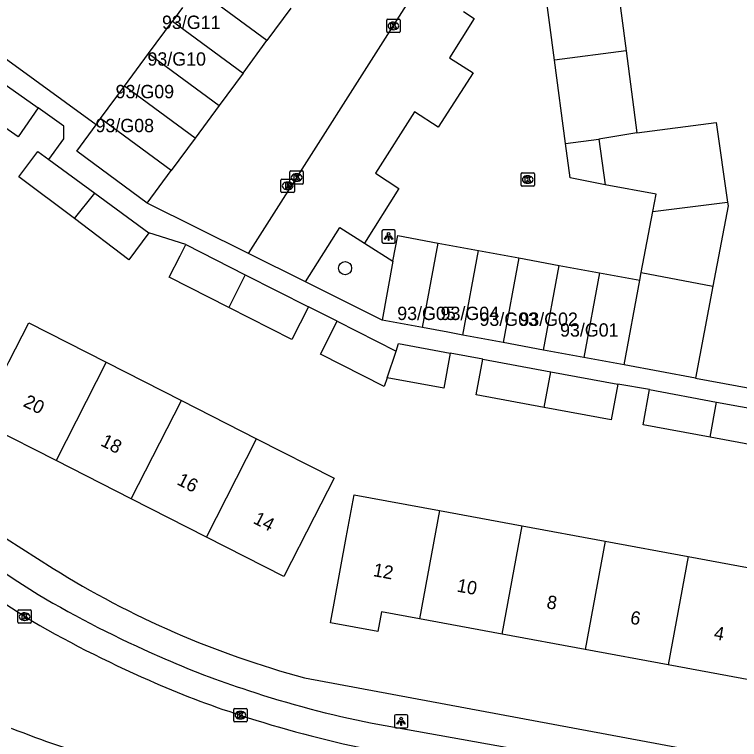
# Model space of a CAD drawing. Extents: x 160557 to 161245, y 385330 to 386505.
# Drawn here: x 161001.8 to 161056.2, y 385939.3 to 385993.6 of the extents above; entities that cross this region are included whole.
import ezdxf

# ---------------------------------------------------------------- set-up
doc = ezdxf.new("R2010")
doc.units = 0
for name, color, linetype in [('IMGEO_Boom', 7, 'Continuous'), ('IMGEO_Kolk', 7, 'Continuous'), ('IMGEO_Lichtpunt', 7, 'Continuous'), ('IMGEO_Pand', 7, 'Continuous'), ('IMGEO_Pand_nummerreeks', 7, 'Continuous'), ('IMGEO_Rijbaan_lokaal_open', 7, 'Continuous'), ('IMGEO_Rioolput', 7, 'Continuous'), ('IMGEO_Voetpad_gesloten', 7, 'Continuous'), ('IMGEO_Voetpad_open', 7, 'Continuous')]:
    doc.layers.add(name, color=color, linetype=linetype)

msp = doc.modelspace()

# ---------------------------------------------------------------- linework, layer by layer
at = {"layer": 'IMGEO_Boom'}
msp.add_circle((161026.612, 385974.634), 0.489, dxfattribs=at)
at = {"layer": 'IMGEO_Kolk'}
for p, q in [((161029.73, 385992.364), (161029.73, 385993.216)), ((161029.805, 385993.29), (161030.657, 385993.29)), ((161030.731, 385993.216), (161030.731, 385992.364)), ((161030.218, 385993.07), (161030.243, 385993.07)), ((161030.657, 385992.29), (161029.805, 385992.29)), ((161030.241, 385992.51), (161030.216, 385992.51)), ((161022.477, 385981.004), (161022.477, 385981.856)), ((161022.552, 385981.93), (161023.404, 385981.93)), ((161022.965, 385981.71), (161022.99, 385981.71)), ((161023.478, 385981.856), (161023.478, 385981.004)), ((161039.806, 385980.848), (161039.806, 385981.7)), ((161039.881, 385981.774), (161040.733, 385981.774)), ((161040.807, 385981.7), (161040.807, 385980.848)), ((161022.988, 385981.15), (161022.963, 385981.15)), ((161040.294, 385981.554), (161040.319, 385981.554)), ((161023.404, 385980.93), (161022.552, 385980.93)), ((161040.733, 385980.774), (161039.881, 385980.774)), ((161040.317, 385980.994), (161040.292, 385980.994)), ((161002.077, 385948.088), (161002.077, 385948.94)), ((161002.152, 385949.014), (161003.004, 385949.014)), ((161002.565, 385948.794), (161002.59, 385948.794)), ((161003.078, 385948.94), (161003.078, 385948.088)), ((161003.004, 385948.014), (161002.152, 385948.014)), ((161002.588, 385948.234), (161002.563, 385948.234)), ((161018.255, 385940.702), (161018.255, 385941.554)), ((161018.33, 385941.628), (161019.182, 385941.628)), ((161019.256, 385941.554), (161019.256, 385940.702)), ((161018.743, 385941.408), (161018.768, 385941.408)), ((161019.182, 385940.628), (161018.33, 385940.628)), ((161018.766, 385940.848), (161018.741, 385940.848))]:
    msp.add_line(p, q, dxfattribs=at)
for points in [[(161029.73, 385992.364), (161029.73, 385993.216)], [(161029.805, 385993.29), (161030.657, 385993.29)], [(161030.731, 385993.216), (161030.731, 385992.364)], [(161030.051, 385992.99), (161030.174, 385992.99), (161030.174, 385992.839), (161030.304, 385992.99), (161030.468, 385992.99), (161030.322, 385992.839), (161030.475, 385992.59), (161030.323, 385992.59), (161030.238, 385992.754), (161030.174, 385992.687), (161030.174, 385992.59), (161030.051, 385992.59), (161030.051, 385992.99)], [(161030.657, 385992.29), (161029.805, 385992.29)], [(161022.477, 385981.004), (161022.477, 385981.856)], [(161022.552, 385981.93), (161023.404, 385981.93)], [(161023.478, 385981.856), (161023.478, 385981.004)], [(161039.806, 385980.848), (161039.806, 385981.7)], [(161039.881, 385981.774), (161040.733, 385981.774)], [(161040.807, 385981.7), (161040.807, 385980.848)], [(161022.798, 385981.63), (161022.921, 385981.63), (161022.921, 385981.479), (161023.051, 385981.63), (161023.215, 385981.63), (161023.069, 385981.479), (161023.222, 385981.23), (161023.07, 385981.23), (161022.985, 385981.394), (161022.921, 385981.327), (161022.921, 385981.23), (161022.798, 385981.23), (161022.798, 385981.63)], [(161040.127, 385981.474), (161040.25, 385981.474), (161040.25, 385981.323), (161040.38, 385981.474), (161040.544, 385981.474), (161040.398, 385981.323), (161040.551, 385981.074), (161040.399, 385981.074), (161040.314, 385981.238), (161040.25, 385981.171), (161040.25, 385981.074), (161040.127, 385981.074), (161040.127, 385981.474)], [(161023.404, 385980.93), (161022.552, 385980.93)], [(161040.733, 385980.774), (161039.881, 385980.774)], [(161002.077, 385948.088), (161002.077, 385948.94)], [(161002.152, 385949.014), (161003.004, 385949.014)], [(161002.398, 385948.714), (161002.521, 385948.714), (161002.521, 385948.563), (161002.651, 385948.714), (161002.815, 385948.714), (161002.669, 385948.563), (161002.822, 385948.314), (161002.67, 385948.314), (161002.585, 385948.478), (161002.521, 385948.411), (161002.521, 385948.314), (161002.398, 385948.314), (161002.398, 385948.714)], [(161003.078, 385948.94), (161003.078, 385948.088)], [(161003.004, 385948.014), (161002.152, 385948.014)], [(161018.255, 385940.702), (161018.255, 385941.554)], [(161018.33, 385941.628), (161019.182, 385941.628)], [(161019.256, 385941.554), (161019.256, 385940.702)], [(161018.576, 385941.328), (161018.699, 385941.328), (161018.699, 385941.177), (161018.829, 385941.328), (161018.993, 385941.328), (161018.847, 385941.177), (161019, 385940.928), (161018.848, 385940.928), (161018.763, 385941.092), (161018.699, 385941.025), (161018.699, 385940.928), (161018.576, 385940.928), (161018.576, 385941.328)], [(161019.182, 385940.628), (161018.33, 385940.628)]]:
    msp.add_lwpolyline(points, dxfattribs=at)
for centre, start, end in [((161029.807, 385993.214), 91.552, 178.448), ((161029.807, 385993.214), 91.552, 178.448), ((161030.655, 385993.214), 1.552, 88.448), ((161030.655, 385993.214), 1.552, 88.448), ((161029.807, 385992.366), 181.552, 268.448), ((161029.807, 385992.366), 181.552, 268.448), ((161030.655, 385992.366), 271.552, 358.448), ((161030.655, 385992.366), 271.552, 358.448), ((161022.554, 385981.854), 91.552, 178.448), ((161022.554, 385981.854), 91.552, 178.448), ((161023.402, 385981.854), 1.552, 88.448), ((161023.402, 385981.854), 1.552, 88.448), ((161039.883, 385981.698), 91.552, 178.448), ((161039.883, 385981.698), 91.552, 178.448), ((161040.731, 385981.698), 1.552, 88.448), ((161040.731, 385981.698), 1.552, 88.448), ((161022.554, 385981.006), 181.552, 268.448), ((161022.554, 385981.006), 181.552, 268.448), ((161023.402, 385981.006), 271.552, 358.448), ((161023.402, 385981.006), 271.552, 358.448), ((161039.883, 385980.85), 181.552, 268.448), ((161039.883, 385980.85), 181.552, 268.448), ((161040.731, 385980.85), 271.552, 358.448), ((161040.731, 385980.85), 271.552, 358.448), ((161002.154, 385948.938), 91.552, 178.448), ((161002.154, 385948.938), 91.552, 178.448), ((161003.002, 385948.938), 1.552, 88.448), ((161003.002, 385948.938), 1.552, 88.448), ((161002.154, 385948.09), 181.552, 268.448), ((161002.154, 385948.09), 181.552, 268.448), ((161003.002, 385948.09), 271.552, 358.448), ((161003.002, 385948.09), 271.552, 358.448), ((161018.332, 385941.552), 91.552, 178.448), ((161018.332, 385941.552), 91.552, 178.448), ((161019.18, 385941.552), 1.552, 88.448), ((161019.18, 385941.552), 1.552, 88.448), ((161018.332, 385940.704), 181.552, 268.448), ((161018.332, 385940.704), 181.552, 268.448), ((161019.18, 385940.704), 271.552, 358.448), ((161019.18, 385940.704), 271.552, 358.448)]:
    msp.add_arc(centre, 0.0765, start, end, dxfattribs=at)
for centre, major_axis, ratio, start_param, end_param in [((161030.217, 385992.79), (-0.387, 0.002), 0.722429, 4.712389, 7.853982), ((161030.242, 385992.79), (-0.39, 0.002), 0.717154, 1.570796, 4.712389), ((161022.964, 385981.43), (-0.387, 0.002), 0.722429, 4.712389, 7.853982), ((161022.989, 385981.43), (-0.39, 0.002), 0.717154, 1.570796, 4.712389), ((161040.293, 385981.274), (-0.387, 0.002), 0.722429, 4.712389, 7.853982), ((161040.318, 385981.274), (-0.39, 0.002), 0.717154, 1.570796, 4.712389), ((161002.564, 385948.514), (-0.387, 0.002), 0.722429, 4.712389, 7.853982), ((161002.589, 385948.514), (-0.39, 0.002), 0.717154, 1.570796, 4.712389), ((161018.742, 385941.128), (-0.387, 0.002), 0.722429, 4.712389, 7.853982), ((161018.767, 385941.128), (-0.39, 0.002), 0.717154, 1.570796, 4.712389)]:
    msp.add_ellipse(centre, major_axis=major_axis, ratio=ratio, start_param=start_param, end_param=end_param, dxfattribs=at)
at = {"layer": 'IMGEO_Lichtpunt'}
for p, q in [((161029.378, 385977.415), (161029.378, 385976.608)), ((161029.378, 385977.415), (161029.378, 385976.608)), ((161030.28, 385977.51), (161029.472, 385977.51)), ((161030.28, 385977.51), (161029.472, 385977.51)), ((161030.374, 385976.608), (161030.374, 385977.415)), ((161030.374, 385976.608), (161030.374, 385977.415)), ((161029.472, 385976.514), (161030.28, 385976.514)), ((161029.472, 385976.514), (161030.28, 385976.514)), ((161030.313, 385941.068), (161030.313, 385940.261)), ((161030.313, 385941.068), (161030.313, 385940.261)), ((161031.215, 385941.163), (161030.407, 385941.163)), ((161031.215, 385941.163), (161030.407, 385941.163)), ((161031.309, 385940.261), (161031.309, 385941.068)), ((161031.309, 385940.261), (161031.309, 385941.068)), ((161030.407, 385940.167), (161031.215, 385940.167)), ((161030.407, 385940.167), (161031.215, 385940.167))]:
    msp.add_line(p, q, dxfattribs=at)
for points in [[(161029.752, 385977.079), (161029.791, 385977.051), (161029.603, 385976.789), (161029.565, 385976.816), (161029.752, 385977.079)], [(161029.854, 385977.031), (161029.901, 385977.031), (161029.901, 385976.709), (161029.854, 385976.709), (161029.854, 385977.031)], [(161029.964, 385977.051), (161030.002, 385977.078), (161030.189, 385976.816), (161030.15, 385976.788), (161029.964, 385977.051)], [(161030.687, 385940.732), (161030.726, 385940.704), (161030.538, 385940.442), (161030.5, 385940.469), (161030.687, 385940.732)], [(161030.789, 385940.684), (161030.836, 385940.684), (161030.836, 385940.362), (161030.789, 385940.362), (161030.789, 385940.684)], [(161030.899, 385940.704), (161030.937, 385940.731), (161031.124, 385940.469), (161031.085, 385940.441), (161030.899, 385940.704)]]:
    msp.add_lwpolyline(points, dxfattribs=at)
for centre in [(161029.877, 385977.213), (161030.812, 385940.866)]:
    msp.add_circle(centre, 0.0994, dxfattribs=at)
for centre, start, end in [((161029.472, 385977.415), 90, 180), ((161029.472, 385977.415), 90, 180), ((161030.28, 385977.415), 0, 90), ((161030.28, 385977.415), 0, 90), ((161029.472, 385976.608), 180, 270), ((161029.472, 385976.608), 180, 270), ((161030.28, 385976.608), 270, 0), ((161030.28, 385976.608), 270, 360), ((161030.407, 385941.068), 90, 180), ((161030.407, 385941.068), 90, 180), ((161031.215, 385941.068), 0, 90), ((161031.215, 385941.068), 0, 90), ((161030.407, 385940.261), 180, 270), ((161030.407, 385940.261), 180, 270), ((161031.215, 385940.261), 270, 0), ((161031.215, 385940.261), 270, 360)]:
    msp.add_arc(centre, 0.0946, start, end, dxfattribs=at)
at = {"layer": 'IMGEO_Pand'}
for points in [[(161046.901, 385996.967), (161047.692, 385990.916)], [(161042.325, 385990.226), (161041.525, 385996.276)], [(161020.75, 385991.692), (161015.459, 385995.591)], [(161014.411, 385994.169), (161013.663, 385993.154)], [(161022.545, 385994.13), (161020.75, 385991.692)], [(161011.867, 385990.717), (161013.663, 385993.154)], [(161013.663, 385993.154), (161018.954, 385989.255)], [(161018.954, 385989.255), (161020.75, 385991.692)], [(161047.692, 385990.916), (161042.325, 385990.226)], [(161047.692, 385990.916), (161048.495, 385984.776)], [(161010.071, 385988.279), (161011.867, 385990.717)], [(161011.867, 385990.717), (161017.158, 385986.818)], [(161043.151, 385983.98), (161042.325, 385990.226)], [(161003.588, 385986.655), (161002.082, 385984.482), (161000, 385985.928), (160997.653, 385987.558), (160999.244, 385989.717)], [(160999.244, 385989.717), (161000, 385989.184), (161003.588, 385986.655)], [(161018.954, 385989.255), (161017.158, 385986.818)], [(161008.275, 385985.842), (161010.071, 385988.279)], [(161015.362, 385984.381), (161010.071, 385988.279)], [(161017.158, 385986.818), (161015.362, 385984.381)], [(161007.936, 385985.383), (161008.153, 385985.677), (161008.275, 385985.842)], [(161013.566, 385981.943), (161008.275, 385985.842)], [(161048.495, 385984.776), (161054.445, 385985.554), (161055.293, 385979.589)], [(161011.77, 385979.506), (161007.745, 385982.472), (161006.479, 385983.405), (161007.936, 385985.383)], [(161015.362, 385984.381), (161013.566, 385981.943)], [(161048.495, 385984.776), (161045.648, 385984.299)], [(161043.151, 385983.98), (161045.648, 385984.299)], [(161045.648, 385984.299), (161046.119, 385980.889)], [(161006.305, 385978.366), (161002.142, 385981.474), (161003.578, 385983.383), (161004.39, 385982.787)], [(161004.39, 385982.787), (161007.836, 385980.257)], [(161011.77, 385979.506), (161013.566, 385981.943)], [(161049.696, 385978.869), (161049.946, 385980.185), (161046.119, 385980.889)], [(161006.305, 385978.366), (161007.836, 385980.257)], [(161007.836, 385980.257), (161011.882, 385977.286)], [(161049.696, 385978.869), (161055.293, 385979.589)], [(161055.293, 385979.589), (161055.333, 385979.308), (161054.187, 385973.279)], [(161048.827, 385974.296), (161049.696, 385978.869)], [(161011.882, 385977.286), (161010.398, 385975.266), (161006.305, 385978.366)], [(161030.202, 385975.145), (161030.559, 385977.077), (161033.586, 385976.518)], [(161017.879, 385971.686), (161013.42, 385973.955), (161014.229, 385975.546), (161014.667, 385976.406)], [(161014.667, 385976.406), (161019.126, 385974.138)], [(161032.414, 385970.174), (161033.586, 385976.518)], [(161033.586, 385976.518), (161036.612, 385975.96)], [(161035.441, 385969.615), (161036.612, 385975.96)], [(161036.612, 385975.96), (161039.638, 385975.401)], [(161030.202, 385975.145), (161029.388, 385970.733)], [(161039.638, 385975.401), (161038.467, 385969.057)], [(161039.638, 385975.401), (161042.665, 385974.842)], [(161041.494, 385968.498), (161042.665, 385974.842)], [(161042.665, 385974.842), (161045.692, 385974.284)], [(161019.126, 385974.138), (161017.879, 385971.686)], [(161019.126, 385974.138), (161023.861, 385971.729)], [(161045.692, 385974.284), (161044.52, 385967.94)], [(161045.692, 385974.284), (161048.718, 385973.725)], [(161048.718, 385973.725), (161048.827, 385974.296)], [(161048.827, 385974.296), (161054.187, 385973.279)], [(161047.548, 385967.381), (161048.718, 385973.725)], [(161054.187, 385973.279), (161052.879, 385966.397)], [(161023.861, 385971.729), (161022.614, 385969.277), (161017.879, 385971.686)], [(161004.933, 385960.205), (161000, 385962.715), (160999.132, 385963.156), (161000, 385964.863), (161001.399, 385967.613), (161002.886, 385970.536), (161008.686, 385967.585)], [(161029.767, 385966.417), (161029.547, 385965.758), (161024.756, 385968.196), (161026.011, 385970.663)], [(161026.011, 385970.663), (161030.433, 385968.413)], [(161032.414, 385970.174), (161029.388, 385970.733)], [(161035.441, 385969.615), (161034.305, 385969.825), (161032.414, 385970.174)], [(161038.467, 385969.057), (161035.441, 385969.615)], [(161030.433, 385968.413), (161030.622, 385968.978), (161034.5, 385968.262)], [(161041.494, 385968.498), (161038.467, 385969.057)], [(161029.767, 385966.417), (161030.433, 385968.413)], [(161034.5, 385968.262), (161034.014, 385965.633), (161029.767, 385966.417)], [(161044.52, 385967.94), (161041.494, 385968.498)], [(161008.686, 385967.585), (161004.933, 385960.205)], [(161008.686, 385967.585), (161014.332, 385964.713)], [(161041.537, 385964.2), (161036.448, 385965.14), (161036.943, 385967.815)], [(161036.943, 385967.815), (161042.031, 385966.874)], [(161047.548, 385967.381), (161044.52, 385967.94)], [(161052.879, 385966.397), (161047.548, 385967.381)], [(161041.537, 385964.2), (161042.031, 385966.874)], [(161042.031, 385966.874), (161047.069, 385965.943)], [(161047.069, 385965.943), (161046.574, 385963.269), (161041.537, 385964.2)], [(161053.984, 385961.964), (161048.954, 385962.894), (161049.441, 385965.527)], [(161049.441, 385965.527), (161054.471, 385964.597)], [(161010.578, 385957.333), (161014.332, 385964.713)], [(161014.332, 385964.713), (161019.977, 385961.842)], [(161053.984, 385961.964), (161054.471, 385964.597)], [(161054.471, 385964.597), (161059.585, 385963.652)], [(161059.585, 385963.652), (161059.099, 385961.019), (161053.984, 385961.964)], [(161019.977, 385961.842), (161025.781, 385958.889), (161024.294, 385955.966), (161022.026, 385951.509), (161016.224, 385954.461)], [(161016.224, 385954.461), (161019.977, 385961.842)], [(161010.578, 385957.333), (161004.933, 385960.205)], [(161016.224, 385954.461), (161010.578, 385957.333)], [(161032.179, 385948.345), (161029.332, 385948.871), (161029.059, 385947.396), (161025.519, 385948.05), (161025.792, 385949.525), (161026.701, 385954.442), (161027.294, 385957.653), (161033.68, 385956.473)], [(161033.68, 385956.473), (161032.179, 385948.345)], [(161033.68, 385956.473), (161039.898, 385955.324)], [(161038.397, 385947.196), (161039.898, 385955.324)], [(161039.898, 385955.324), (161046.116, 385954.175)], [(161046.116, 385954.175), (161044.615, 385946.047)], [(161046.116, 385954.175), (161052.333, 385953.026)], [(161052.333, 385953.026), (161050.832, 385944.898)], [(161052.333, 385953.026), (161058.551, 385951.877)], [(161038.397, 385947.196), (161032.179, 385948.345)], [(161044.615, 385946.047), (161038.397, 385947.196)], [(161050.832, 385944.898), (161044.615, 385946.047)], [(161057.05, 385943.749), (161050.832, 385944.898)]]:
    msp.add_lwpolyline(points, dxfattribs=at)
at = {"layer": 'IMGEO_Rijbaan_lokaal_open'}
for points in [[(161019.362, 385975.725), (161032.442, 385996.293)], [(161035.482, 385993.862), (161036.297, 385993.354), (161034.444, 385990.41), (161036.209, 385989.28), (161033.603, 385985.194), (161031.813, 385986.345), (161028.881, 385981.746), (161030.635, 385980.609), (161028.054, 385976.511)], [(161046.119, 385980.889), (161043.5, 385981.394), (161043.151, 385983.98)], [(161019.362, 385975.725), (161011.77, 385979.506)], [(161028.054, 385976.511), (161030.202, 385975.145)], [(161002.589, 385948.505), (160999.999, 385950.177), (160998.189, 385951.341), (160986.724, 385958.988), (160973.667, 385967.66)]]:
    msp.add_lwpolyline(points, dxfattribs=at)
for centre, radius, start, end in [((161046.652, 386023.307), 86.816, 239.49922, 246.411), ((161039.17, 386004.728), 66.797, 245.91547, 252.20158), ((161044.383, 386018.65), 81.65, 251.7048, 258.62704), ((161031.746, 386016.467), 82.062, 248.41375, 259.00106)]:
    msp.add_arc(centre, radius, start, end, dxfattribs=at)
at = {"layer": 'IMGEO_Rioolput'}
for p, q in [((161021.803, 385980.375), (161021.803, 385981.227)), ((161021.878, 385981.301), (161022.73, 385981.301)), ((161022.804, 385981.227), (161022.804, 385980.375)), ((161022.291, 385981.081), (161022.316, 385981.081)), ((161022.73, 385980.301), (161021.878, 385980.301)), ((161022.314, 385980.521), (161022.289, 385980.521))]:
    msp.add_line(p, q, dxfattribs=at)
for points in [[(161021.803, 385980.375), (161021.803, 385981.227)], [(161021.878, 385981.301), (161022.73, 385981.301)], [(161022.804, 385981.227), (161022.804, 385980.375)], [(161022.392, 385980.999), (161022.14, 385981.001), (161022.14, 385980.601)], [(161022.14, 385980.601), (161022.264, 385980.601), (161022.264, 385980.763), (161022.275, 385980.763)], [(161022.318, 385980.92), (161022.264, 385980.92), (161022.264, 385980.839)], [(161022.264, 385980.839), (161022.316, 385980.839)], [(161022.322, 385980.734), (161022.393, 385980.601), (161022.533, 385980.601), (161022.468, 385980.727)], [(161022.73, 385980.301), (161021.878, 385980.301)]]:
    msp.add_lwpolyline(points, dxfattribs=at)
for centre, radius, start, end in [((161021.88, 385981.225), 0.0765, 91.552, 178.448), ((161021.88, 385981.225), 0.0765, 91.552, 178.448), ((161022.728, 385981.225), 0.0765, 1.552, 88.448), ((161022.728, 385981.225), 0.0765, 1.552, 88.448), ((161022.274, 385980.71), 0.0533, 26.0293, 88.6989), ((161022.3, 385981.028), 0.19, 274.7715, 282.9687), ((161022.324, 385980.824), 0.0964, 77.0061, 93.1865), ((161022.338, 385980.881), 0.0378, 276.6634, 79.6772), ((161022.391, 385980.889), 0.109, 350.3612, 89.416), ((161022.389, 385980.889), 0.112, 277.5842, 350.9817), ((161022.373, 385980.674), 0.108, 29.5134, 73.7905), ((161021.88, 385980.377), 0.0765, 181.552, 268.448), ((161021.88, 385980.377), 0.0765, 181.552, 268.448), ((161022.728, 385980.377), 0.0765, 271.552, 358.448), ((161022.728, 385980.377), 0.0765, 271.552, 358.448)]:
    msp.add_arc(centre, radius, start, end, dxfattribs=at)
for centre, major_axis, ratio, start_param, end_param in [((161022.29, 385980.801), (-0.387, 0.002), 0.722429, 4.712389, 7.853982), ((161022.315, 385980.801), (-0.39, 0.002), 0.717154, 1.570796, 4.712389)]:
    msp.add_ellipse(centre, major_axis=major_axis, ratio=ratio, start_param=start_param, end_param=end_param, dxfattribs=at)
at = {"layer": 'IMGEO_Voetpad_gesloten'}
for points in [[(161007.936, 385985.383), (160994.121, 385995.449)], [(161004.39, 385982.787), (161005.527, 385984.336), (161005.527, 385985.288), (161003.588, 385986.655)], [(161014.667, 385976.406), (161011.882, 385977.286)], [(161023.629, 385973.601), (161019.362, 385975.725)], [(161029.388, 385970.733), (161023.629, 385973.601)], [(161026.011, 385970.663), (161023.861, 385971.729)], [(161036.943, 385967.815), (161034.5, 385968.262)], [(161049.441, 385965.527), (161047.069, 385965.943)], [(161052.879, 385966.397), (161063.228, 385964.5)]]:
    msp.add_lwpolyline(points, dxfattribs=at)
at = {"layer": 'IMGEO_Voetpad_open'}
for points in [[(161023.629, 385973.601), (161026.208, 385977.691), (161028.054, 385976.511)], [(160972.379, 385973.71), (161000, 385955.113), (161004.713, 385952.127)], [(160977.636, 385967.398), (160987.82, 385960.634), (161000, 385952.51), (161001.799, 385951.331), (161003.597, 385950.169)], [(161023.564, 385943.934), (161062.346, 385936.7), (161063.954, 385936.4), (161074.492, 385934.434)], [(161028.631, 385940.519), (161053.33, 385936.099), (161059.612, 385934.962)]]:
    msp.add_lwpolyline(points, dxfattribs=at)
for centre, radius, start, end in [((161041.465, 386010.905), 69.322, 237.98357, 255.03508), ((161045.815, 386021.683), 83.045, 239.44492, 246.49682), ((161038.477, 386002.912), 62.91, 245.8074, 252.30563), ((161044.257, 386018.18), 79.217, 251.67909, 258.62347)]:
    msp.add_arc(centre, radius, start, end, dxfattribs=at)

# ---------------------------------------------------------------- texts
at = {"layer": 'IMGEO_Pand_nummerreeks'}
for s, p in [('93/G11', (161012.88, 385992.564)), ('93/G10', (161011.789, 385989.812)), ('93/G09', (161009.4, 385987.37)), ('93/G08', (161007.894, 385984.825)), ('93/G05', (161030.521, 385970.745)), ('93/G04', (161033.774, 385970.745)), ('93/G03', (161036.691, 385970.306)), ('93/G02', (161039.685, 385970.306)), ('93/G01', (161042.733, 385969.5))]:
    msp.add_text(s, height=1, dxfattribs=at).set_placement(p)
for s, rotation, p in [('20', 333.0347, (161002.403, 385964.32)), ('18', 333.0347, (161008.207, 385961.366)), ('16', 333.0347, (161013.928, 385958.457)), ('14', 333.0347, (161019.651, 385955.545)), ('12', 349.5306, (161028.661, 385951.558)), ('10', 349.5306, (161034.942, 385950.397)), ('8', 349.5306, (161041.671, 385949.154)), ('6', 349.5306, (161047.942, 385947.994)), ('4', 349.5306, (161054.217, 385946.835))]:
    msp.add_text(s, height=1, rotation=rotation, dxfattribs=at).set_placement(p)

doc.saveas('drawing.dxf')
